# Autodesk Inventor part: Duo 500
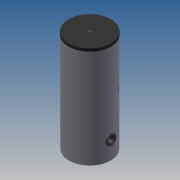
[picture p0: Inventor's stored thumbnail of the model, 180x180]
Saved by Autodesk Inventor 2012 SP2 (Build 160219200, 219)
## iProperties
Created: 2014-05
Part Number: Duo 500
Material: Default
Document SubType Name: Modeling
Designer: michel
Density: 1 g/cm^3
Author: michel
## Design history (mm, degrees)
sketch "Sketch1"
  geometry: C1 r 375 at (0, 0); 1 further point
  constraints: 1 centre point, 1 coincident
  dimensions: "d0" = 750 diameter of C1
extrude "Extrusion1" new body sketch "Sketch1" distance "d1" = 1830; taper "d2" = 0 deg
sketch "Sketch2"
  geometry: L1 (-375, 1830)-(375, 1830) reference; L2 (-375, 0)-(375, 0) reference; L3 (375, 0)-(375, 1830) reference; L4 (375, 1830)-(380, 1830); L5 (380, 1830)-(380, 1780); L6 (380, 1780)-(375, 1780); L7 (375, 1780)-(375, 1830); L8 (0, -326)-(0, 1956) reference; 1 further point
  constraints: 8 end point, 2 parallel, 1 horizontal, 1 perpendicular
  dimensions: "d3" = 5 distance of L5.end L6.end; "d4" = 50 distance of L4.end L5.end
revolve "Revolution1" sketch "Sketch2" stored, may be unused: angle "d5" = 90 deg
workplane "Work Plane1"
workplane "Work Plane2"
workplane "Work Plane3"
workplane "Work Plane4"
workplane "Work Plane5"
workplane "Work Plane6"
sketch "Sketch3"
  geometry: L1 (525, 1670)-(-525, 1670) reference; L2 (526.398, 990)-(-525.233, 990) reference; L3 (526.398, 890)-(-525.233, 890) reference; L4 (525, 330)-(-525, 330) reference; L5 (525, 70)-(-525, 70) reference; L6 (375, 0)-(375, 1780) reference; L7 (375, 1670)-(335, 1670); L8 (335, 1670)-(335, 1686.625); L9 (335, 1686.625)-(375, 1686.625); L10 (375, 1686.625)-(375, 1670); L11 (375, 990)-(335, 990); L12 (335, 990)-(335, 1003.22); L13 (335, 1003.22)-(375, 1003.22); L14 (375, 1003.22)-(375, 990); L15 (335, 1654.625)-(335, 1653.375); L16 (335, 1653.375)-(376, 1653.375); L17 (376, 1653.375)-(376, 1654.625); L18 (376, 1654.625)-(335, 1654.625); L19 (335, 890)-(335, 906.625); L20 (375, 890)-(335, 890); L21 (335, 906.625)-(375, 906.625); L22 (375, 906.625)-(375, 890); L23 (335, 874.625)-(335, 873.375); L24 (335, 873.375)-(376, 873.375); L25 (376, 873.375)-(376, 874.625); L26 (376, 874.625)-(335, 874.625); L27 (335.165, 346.625)-(375.165, 346.625); L28 (335.165, 330)-(335.165, 346.625); L29 (375.165, 330)-(335.165, 330); L30 (375.165, 346.625)-(375.165, 330); L31 (376.165, 314.625)-(335.165, 314.625); L32 (335.165, 314.625)-(335.165, 313.375); L33 (335.165, 313.375)-(376.165, 313.375); L34 (376.165, 313.375)-(376.165, 314.625); L35 (335, 86.625)-(375, 86.625); L36 (335, 70)-(335, 86.625); L37 (375, 70)-(335, 70); L38 (375, 86.625)-(375, 70); L39 (376, 54.625)-(335, 54.625); L40 (335, 54.625)-(335, 53.375); L41 (335, 53.375)-(376, 53.375); L42 (376, 53.375)-(376, 54.625); L43 (335, 976.78)-(375, 976.78); L44 (335, 977.75)-(335, 976.78); L45 (375, 976.78)-(376, 976.78); L46 (376, 976.78)-(376, 977.75); L47 (376, 977.75)-(335, 977.75); 2 further points
  constraints: 82 end point, 12 parallel, 6 horizontal, 6 perpendicular, 2 point on line
  dimensions: "d19" = 40 distance of L8.end L9.end; "d21" = 40 distance of L12.end L13.end; "d68" = 15.375 distance between parallel lines of L1 L18; "d70" = 16.625 distance between parallel lines of L1 L9; "d73" = 40 distance of L19.end L21.end; "d74" = 40 distance of L27.start L27.end; "d75" = 40 distance of L35.start L35.end; "d76" = 16.625 distance between parallel lines of L3 L21; "d77" = 1.25 distance between parallel lines of L26 L24; "d78" = 15.375 distance between parallel lines of L3 L26; "d79" = 16.625 distance between parallel lines of L4 L27; "d80" = 1.25 distance between parallel lines of L31 L33; "d81" = 15.375 distance between parallel lines of L4 L31; "d82" = 16.625 distance between parallel lines of L5 L35; "d83" = 1.25 distance between parallel lines of L39 L41; "d84" = 15.375 distance between parallel lines of L5 L39; "d85" = 13.22 distance between parallel lines of L2 L13; "d90" = 0.97 distance between parallel lines of L47 L43; "d91" = 12.25 distance between parallel lines of L2 L47
revolve "Revolution2" stored, may be unused: angle "d23" = 90 deg
sketch "Sketch5"
  geometry: L1 (-375, 0)-(-375, 1780) reference; L2 (-375, 0)-(-375, 327); L3 (-249, 327)-(-623, 327); L4 (-375, 327)-(-387.5, 327); L5 (-387.5, 327)-(-387.5, 417); L6 (-387.5, 417)-(-375, 417); L7 (-375, 417)-(-375, 327); 1 further point
  constraints: 12 end point, 2 parallel, 2 perpendicular, 1 horizontal, 1 point on line
  dimensions: "d35" = 327 distance of L1.start L2.end; "d36" = 12.5 distance of L5.end L6.end; "d37" = 90 distance of L4.end L5.end
revolve "Revolution7" sketch "Sketch5" stored, may be unused: angle "d38" = 90 deg
sketch "Sketch6"
  geometry: C1 r 62.5 at (0, 0); A1 r 90 centre (0, 0) between (90, 0) and (-90, 0) reference; 1 further point
  constraints: 1 centre point, 1 coincident
  dimensions: "d39" = 125 diameter of C1
extrude "Extrusion3" join sketch "Sketch6" stored distance "d40" = 40; taper "d41" = 0 deg
sketch "Sketch7"
  geometry: C1 r 90 at (0, 0) reference; C2 r 55 at (0, 0); 1 further point
  constraints: 1 centre point, 1 coincident
  dimensions: "d42" = 110 diameter of C2
extrude "Extrusion4" cut sketch "Sketch7" distance "d43" = 80; taper "d44" = 0 deg
sketch "Sketch8"
  geometry: C1 r 380 at (0, 0) reference; C2 r 20.955 at (0, 0)
  constraints: 1 centre point, 1 coincident
  dimensions: "d45" = 41.91 diameter of C2
extrude "Extrusion5" join sketch "Sketch8" distance "d46" = 2; taper "d47" = 0 deg
sketch "Sketch9"
  geometry: C1 r 20.955 at (0, 0) reference; C2 r 19.625 at (0, 0)
  constraints: 1 centre point, 1 coincident
  dimensions: "d48" = 39.25 diameter of C2
extrude "Extrusion6" cut sketch "Sketch9" distance "d49" = 40; taper "d50" = 0 deg
workplane "Work Plane8"
sketch "Sketch10"
  geometry: L1 (0, 375)-(1780, 375) reference; L2 (990, -731.182)-(990, 731.182) reference; L3 (990, 375)-(1013.9, 375); L4 (1013.9, 375)-(1013.9, 335); L5 (1013.9, 335)-(990, 335); L6 (990, 335)-(990, 375); 1 further point
  constraints: 8 end point, 2 parallel, 2 point on line, 1 horizontal, 1 perpendicular
  dimensions: "d52" = 23.9 distance of L4.end L5.end; "d53" = 40 distance of L3.end L4.end
revolve "Revolution8" sketch "Sketch10" stored, may be unused: angle "d54" = 90 deg
sketch "Sketch11"
  geometry: C1 r 22.625 at (0, 0); A1 r 23.9 centre (0, 0) between (23.9, 0) and (-23.9, 0) reference; 1 further point
  constraints: 1 centre point, 1 coincident
  dimensions: "d55" = 45.25 diameter of C1
extrude "Extrusion7" cut sketch "Sketch11" distance "d56" = 40; taper "d57" = 0 deg
sketch "Sketch12"
  geometry: C1 r 22.625 at (0, 0) reference; A1 r 23.9 centre (0, 0) between (-23.9, 0) and (23.9, 0) reference; A2 r 23.9 centre (0, 0) between (23.9, 0) and (-23.9, 0) reference; 1 further point
extrude "Extrusion8" join sketch "Sketch12" distance "d58" = 1; taper "d59" = 0 deg
revolve "Revolution9" stored, may be unused: angle "d69" = 90 deg
revolve "Revolution10" stored, may be unused: angle "d92" = 90 deg
revolve "Revolution11" stored, may be unused: angle "d93" = 90 deg
revolve "Revolution12" stored, may be unused: angle "d94" = 90 deg
revolve "Revolution13" stored, may be unused: angle "d95" = 90 deg
revolve "Revolution14" stored, may be unused: angle "d96" = 90 deg
revolve "Revolution15" stored, may be unused: angle "d97" = 90 deg
revolve "Revolution16" stored, may be unused: angle "d98" = 90 deg
revolve "Revolution17" stored, may be unused: angle "d99" = 90 deg
body "Solid1"
node "Projected Loop1"
other parameters: "d12" = 0, "d51" = 35 deg
